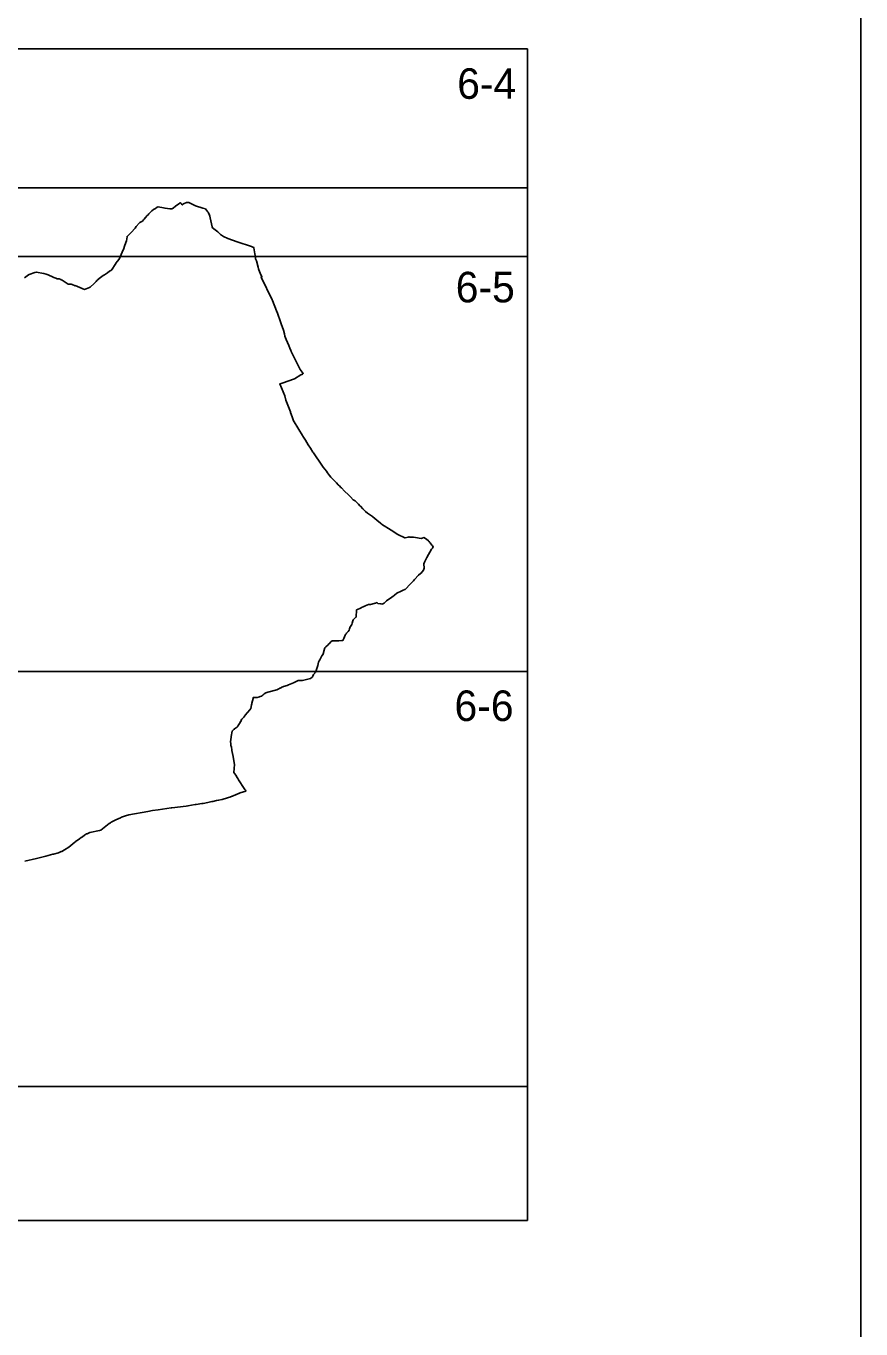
# Model space of a CAD drawing. Extents: x -449577 to -436680, y -1132317 to -1125726.
# Drawn here: x -441418.4 to -441167.1, y -1131954.1 to -1131561.7 of the extents above; entities that cross this region are included whole.
import ezdxf

# ---------------------------------------------------------------- set-up
doc = ezdxf.new("R2010")
doc.units = 0
for name, color, linetype in [('Vrstva 1', 7, 'Continuous'), ('Vrstva 10', 7, 'Continuous'), ('Vrstva 4', 7, 'Continuous')]:
    doc.layers.add(name, color=color, linetype=linetype)

msp = doc.modelspace()

# ---------------------------------------------------------------- linework, layer by layer
at = {"layer": 'Vrstva 1'}
msp.add_lwpolyline([(-442652.08, -1131267.17), (-442652.08, -1132317.17), (-441167.08, -1132317.17), (-441167.08, -1131267.17)], close=True, dxfattribs=at)
msp.add_lwpolyline([(-441418.79, -1131813.29), (-441415.25, -1131812.42), (-441412.48, -1131811.75), (-441411.81, -1131811.54), (-441410.32, -1131811.18), (-441410.11, -1131811.12), (-441408.68, -1131810.73), (-441408.08, -1131810.47), (-441407.86, -1131810.37), (-441407.7, -1131810.31), (-441406.88, -1131809.86), (-441406.82, -1131809.82), (-441405.51, -1131809.04), (-441404.36, -1131807.99), (-441403.71, -1131807.49), (-441403.58, -1131807.38), (-441403.56, -1131807.37), (-441403.4, -1131807.24), (-441403.25, -1131807.14), (-441402.45, -1131806.58), (-441402.39, -1131806.54), (-441402.32, -1131806.49), (-441401.81, -1131806.14), (-441401.44, -1131805.88), (-441400.78, -1131805.42), (-441400.19, -1131805.01), (-441400.03, -1131805.04), (-441400.02, -1131805.04), (-441400, -1131805.02), (-441399.27, -1131804.63), (-441396.31, -1131804.05), (-441395.89, -1131803.9), (-441393.86, -1131802.27), (-441393.39, -1131801.93), (-441393.36, -1131801.91), (-441393, -1131801.65), (-441392.82, -1131801.53), (-441391.43, -1131800.83), (-441390.02, -1131800.19), (-441389.72, -1131800.04), (-441388.46, -1131799.58), (-441387.46, -1131799.33), (-441381.75, -1131798.27), (-441380.33, -1131798.01), (-441378.62, -1131797.76), (-441374.75, -1131797.19), (-441374.51, -1131797.16), (-441370.21, -1131796.64), (-441369.68, -1131796.58), (-441367.53, -1131796.22), (-441367.21, -1131796.17), (-441365.55, -1131795.9), (-441365.15, -1131795.83), (-441363.74, -1131795.54), (-441362.45, -1131795.27), (-441362.24, -1131795.23), (-441361.07, -1131795), (-441360.4, -1131794.87), (-441360.38, -1131794.87), (-441359.47, -1131794.66), (-441359.4, -1131794.64), (-441358.75, -1131794.48), (-441358.4, -1131794.37), (-441357.51, -1131794.08), (-441357.07, -1131793.93), (-441356.42, -1131793.69), (-441356.3, -1131793.65), (-441355.21, -1131793.16), (-441355.21, -1131793.16), (-441355.09, -1131793.12), (-441354.44, -1131792.89), (-441354.35, -1131792.86), (-441353.92, -1131792.7), (-441352.26, -1131792.12), (-441352.28, -1131792.07), (-441352.39, -1131791.9), (-441352.55, -1131791.67), (-441352.77, -1131791.35), (-441354.47, -1131788.71), (-441354.68, -1131788.36), (-441354.85, -1131788.09), (-441355.29, -1131787.38), (-441355.82, -1131786.53), (-441355.66, -1131784.17), (-441355.65, -1131784.08), (-441356.04, -1131781.78), (-441356.04, -1131781.76), (-441356.05, -1131781.74), (-441356.05, -1131781.74), (-441356.05, -1131781.71), (-441356.46, -1131779.88), (-441356.47, -1131779.69), (-441356.53, -1131778.89), (-441356.63, -1131778.61), (-441356.64, -1131778.59), (-441356.75, -1131778.37), (-441356.79, -1131778.29), (-441356.8, -1131777.91), (-441356.83, -1131777.21), (-441356.78, -1131776.72), (-441356.78, -1131776.7), (-441356.69, -1131775.84), (-441356.67, -1131775.73), (-441356.38, -1131774.09), (-441356.3, -1131774.01), (-441356, -1131773.67), (-441355.94, -1131773.6), (-441355.68, -1131773.48), (-441355.62, -1131773.42), (-441355.36, -1131773.22), (-441355.13, -1131773.04), (-441354.92, -1131772.88), (-441354.86, -1131772.84), (-441354.78, -1131772.71), (-441354.7, -1131772.59), (-441354.59, -1131772.42), (-441354.37, -1131772.09), (-441353.95, -1131771.44), (-441353.82, -1131771.19), (-441353.81, -1131771.18), (-441353.67, -1131770.89), (-441353.62, -1131770.8), (-441353.44, -1131770.47), (-441353.3, -1131770.32), (-441353, -1131770.01), (-441352.83, -1131769.83), (-441352.55, -1131769.48), (-441352.42, -1131769.31), (-441351.73, -1131768.46), (-441351.07, -1131767.65), (-441350.78, -1131767.29), (-441350.54, -1131766.12), (-441350.48, -1131765.89), (-441350.41, -1131765.61), (-441350.09, -1131764.3), (-441350.01, -1131764.02), (-441350.01, -1131763.99), (-441349.99, -1131763.94), (-441349.83, -1131763.93), (-441349.81, -1131763.93), (-441349.57, -1131763.93), (-441348.88, -1131763.91), (-441348.87, -1131763.91), (-441348.84, -1131763.91), (-441348.16, -1131763.73), (-441347.96, -1131763.67), (-441347.54, -1131763.56), (-441347.52, -1131763.55), (-441347.46, -1131763.49), (-441347.16, -1131763.21), (-441347.04, -1131763.13), (-441346.7, -1131762.87), (-441346.28, -1131762.55), (-441346.21, -1131762.53), (-441345.65, -1131762.37), (-441342.95, -1131761.61), (-441342.36, -1131761.34), (-441342.03, -1131761.18), (-441341.98, -1131761.16), (-441341.88, -1131761.11), (-441341.52, -1131760.93), (-441341.47, -1131760.91), (-441341.44, -1131760.89), (-441341.43, -1131760.89), (-441341.4, -1131760.87), (-441341.09, -1131760.72), (-441341.03, -1131760.68), (-441340.92, -1131760.63), (-441339.84, -1131760.3), (-441339.41, -1131760.12), (-441338.89, -1131759.9), (-441337.88, -1131759.49), (-441336.46, -1131758.86), (-441336.32, -1131758.85), (-441335.19, -1131758.8), (-441332.79, -1131758.24), (-441332.26, -1131757.84), (-441332.19, -1131757.72), (-441332.1, -1131757.54), (-441331.84, -1131757.03), (-441331.49, -1131756.6), (-441331.47, -1131756.57), (-441331.26, -1131756.28), (-441331.15, -1131756.12), (-441331.14, -1131756.11), (-441330.6, -1131754.33), (-441330.59, -1131754.3), (-441330.39, -1131753.35), (-441330.13, -1131752.89), (-441329.94, -1131752.56), (-441329.39, -1131751.44), (-441329.01, -1131750.93), (-441328.98, -1131750.8), (-441328.91, -1131750.5), (-441328.88, -1131750.36), (-441328.82, -1131750.11), (-441328.8, -1131750.01), (-441328.48, -1131749), (-441328.47, -1131748.99), (-441328.18, -1131748.71), (-441327.52, -1131748.08), (-441327.47, -1131748.03), (-441327, -1131747.55), (-441326.74, -1131747.29), (-441326.64, -1131747.18), (-441326.27, -1131746.86), (-441326.23, -1131746.86), (-441326.22, -1131746.86), (-441325.81, -1131746.85), (-441325.64, -1131746.86), (-441325.01, -1131746.88), (-441324.3, -1131746.88), (-441323.33, -1131746.79), (-441323.3, -1131746.79), (-441323.05, -1131746.76), (-441322.83, -1131746.4), (-441322.78, -1131746.27), (-441322.76, -1131746.22), (-441322.74, -1131746.16), (-441322.38, -1131745.14), (-441322.24, -1131744.97), (-441322.14, -1131744.86), (-441322.1, -1131744.82), (-441322.04, -1131744.74), (-441321.92, -1131744.61), (-441321.65, -1131744.29), (-441321.56, -1131744.19), (-441321.46, -1131744.07), (-441321.12, -1131743.68), (-441321.05, -1131743.29), (-441320.99, -1131742.98), (-441320.92, -1131742.85), (-441320.37, -1131741.93), (-441320.26, -1131741.54), (-441320.07, -1131740.84), (-441319.95, -1131740.55), (-441319.66, -1131740.28), (-441319.11, -1131739.77), (-441319.04, -1131739.71), (-441318.94, -1131737.6), (-441317.92, -1131737.11), (-441317.52, -1131736.9), (-441317.27, -1131736.77), (-441316.98, -1131736.61), (-441316.76, -1131736.53), (-441316.42, -1131736.4), (-441316.37, -1131736.39), (-441315.28, -1131735.98), (-441315.27, -1131735.98), (-441314.78, -1131735.92), (-441314.7, -1131735.9), (-441313.67, -1131735.64), (-441313.52, -1131735.6), (-441313.43, -1131735.57), (-441313.26, -1131735.52), (-441312.73, -1131735.35), (-441312.73, -1131735.35), (-441312.72, -1131735.36), (-441312.72, -1131735.36), (-441312.69, -1131735.42), (-441312.56, -1131735.64), (-441311.68, -1131735.74), (-441311.48, -1131735.76), (-441311.12, -1131735.8), (-441311.03, -1131735.76), (-441310.6, -1131735.58), (-441309.95, -1131734.87), (-441308.31, -1131733.71), (-441308.22, -1131733.64), (-441308.05, -1131733.53), (-441307.54, -1131733.11), (-441306.79, -1131732.51), (-441305.52, -1131731.94), (-441304.9, -1131731.67), (-441304.36, -1131731.43), (-441304.3, -1131731.4), (-441302.65, -1131729.73), (-441301.81, -1131728.84), (-441301.45, -1131728.46), (-441300.26, -1131727.1), (-441299.66, -1131726.64), (-441299.61, -1131726.6), (-441298.77, -1131725.59), (-441298.57, -1131725.02), (-441298.66, -1131723.69), (-441298.44, -1131723.2), (-441297.8, -1131721.75), (-441296.34, -1131719.27), (-441296.31, -1131719.22), (-441296.31, -1131719.22), (-441296.29, -1131719.19), (-441296.26, -1131719.15), (-441296.11, -1131718.96), (-441295.85, -1131718.62), (-441296.11, -1131718.32), (-441296.25, -1131718.1), (-441296.72, -1131717.36), (-441296.92, -1131717.17), (-441297.07, -1131717.01), (-441297.26, -1131716.81), (-441297.84, -1131716.24), (-441298.69, -1131715.77), (-441299.14, -1131715.95), (-441299.47, -1131716.07), (-441301.22, -1131715.8), (-441301.83, -1131715.71), (-441301.97, -1131715.7), (-441302.56, -1131715.68), (-441302.94, -1131715.63), (-441303.1, -1131715.6), (-441303.14, -1131715.6), (-441303.17, -1131715.59), (-441303.17, -1131715.59), (-441303.2, -1131715.6), (-441303.3, -1131715.63), (-441303.43, -1131715.66), (-441304.33, -1131715.9), (-441304.4, -1131715.87), (-441306.47, -1131714.83), (-441308.49, -1131713.55), (-441311.4, -1131711.73), (-441311.56, -1131711.59), (-441311.6, -1131711.56), (-441311.69, -1131711.48), (-441312.83, -1131710.55), (-441313.98, -1131709.5), (-441314.09, -1131709.4), (-441315.3, -1131708.64), (-441315.58, -1131708.41), (-441316.21, -1131707.91), (-441316.52, -1131707.67), (-441317.02, -1131707.14), (-441317.74, -1131706.38), (-441317.89, -1131706.22), (-441318.35, -1131705.73), (-441319.32, -1131704.7), (-441319.52, -1131704.59), (-441319.52, -1131704.59), (-441319.7, -1131704.5), (-441319.9, -1131704.4), (-441320.73, -1131703.57), (-441321.36, -1131702.94), (-441322.54, -1131701.77), (-441323.47, -1131700.83), (-441323.63, -1131700.68), (-441324.07, -1131700.23), (-441324.31, -1131699.99), (-441324.4, -1131699.9), (-441324.44, -1131699.86), (-441324.96, -1131699.34), (-441325.6, -1131698.69), (-441325.68, -1131698.61), (-441325.7, -1131698.59), (-441325.85, -1131698.44), (-441326.68, -1131697.6), (-441327.06, -1131697.1), (-441327.34, -1131696.73), (-441327.66, -1131696.3), (-441328.02, -1131695.82), (-441328.97, -1131694.56), (-441329.34, -1131694.02), (-441331.88, -1131690.28), (-441332.05, -1131690.02), (-441332.82, -1131688.83), (-441333.49, -1131687.82), (-441334.33, -1131686.49), (-441335.13, -1131685.22), (-441335.21, -1131685.09), (-441336.3, -1131683.24), (-441337.98, -1131680.39), (-441337.98, -1131680.38), (-441337.98, -1131680.38), (-441337.99, -1131680.38), (-441338.32, -1131679.4), (-441338.77, -1131678.1), (-441338.83, -1131677.9), (-441340.21, -1131674.39), (-441340.5, -1131673.14), (-441341.98, -1131669.46), (-441341.35, -1131669.26), (-441337.63, -1131668.02), (-441335.66, -1131666.8), (-441335.48, -1131666.69), (-441335.42, -1131666.65), (-441335.22, -1131666.53), (-441334.95, -1131666.36), (-441335.87, -1131665.17), (-441337.28, -1131662.39), (-441338.03, -1131660.92), (-441338.56, -1131659.76), (-441338.58, -1131659.72), (-441338.64, -1131659.59), (-441338.65, -1131659.56), (-441338.67, -1131659.53), (-441338.71, -1131659.44), (-441339.04, -1131658.71), (-441339.36, -1131657.92), (-441340.07, -1131656.15), (-441340.48, -1131655.11), (-441340.63, -1131654.48), (-441340.89, -1131653.35), (-441341.63, -1131651.46), (-441341.83, -1131650.86), (-441342.77, -1131648.23), (-441343.04, -1131647.51), (-441344.23, -1131644.42), (-441344.3, -1131644.24), (-441344.33, -1131644.16), (-441347.68, -1131637.35), (-441347.37, -1131637.21), (-441347.35, -1131637.2), (-441347.45, -1131637.03), (-441347.53, -1131636.93), (-441347.7, -1131636.7), (-441347.76, -1131636.62), (-441348.37, -1131635.14), (-441348.42, -1131634.85), (-441348.52, -1131634.39), (-441348.53, -1131634.33), (-441349.04, -1131632.49), (-441349.34, -1131631.86), (-441349.35, -1131631.78), (-441349.39, -1131631.42), (-441349.53, -1131630.33), (-441349.81, -1131628.49), (-441349.87, -1131628.47), (-441350.17, -1131628.37), (-441350.55, -1131628.11), (-441350.56, -1131628.11), (-441354.86, -1131626.7), (-441357.65, -1131625.72), (-441358.96, -1131625.1), (-441359.93, -1131624.54), (-441360.65, -1131623.76), (-441362.33, -1131622.49), (-441362.39, -1131622.19), (-441362.97, -1131619.49), (-441363.12, -1131618.95), (-441363.3, -1131618.44), (-441363.35, -1131618.28), (-441363.6, -1131617.76), (-441363.85, -1131617.45), (-441364.43, -1131616.76), (-441365.18, -1131616.55), (-441367.36, -1131615.89), (-441369.45, -1131614.93), (-441370.07, -1131614.93), (-441371.02, -1131615.3), (-441371.15, -1131615.39), (-441371.22, -1131615.44), (-441371.36, -1131615.54), (-441371.4, -1131615.57), (-441371.42, -1131615.55), (-441371.63, -1131615.3), (-441371.88, -1131615.02), (-441371.96, -1131614.92), (-441372.05, -1131614.96), (-441372.56, -1131615.35), (-441372.75, -1131615.5), (-441373.42, -1131616.02), (-441374.17, -1131616.58), (-441374.51, -1131616.8), (-441375.1, -1131616.76), (-441376.58, -1131616.61), (-441377.04, -1131616.52), (-441378.63, -1131616.2), (-441378.93, -1131616.31), (-441379.49, -1131616.66), (-441380.04, -1131616.98), (-441380.53, -1131617.44), (-441381.06, -1131617.93), (-441381.46, -1131618.32), (-441381.47, -1131618.33), (-441381.8, -1131618.67), (-441381.93, -1131618.81), (-441382.44, -1131619.36), (-441382.89, -1131619.91), (-441383.05, -1131620.1), (-441383.41, -1131620.53), (-441384.15, -1131620.86), (-441384.17, -1131620.86), (-441384.37, -1131621.11), (-441385.23, -1131622.13), (-441385.61, -1131622.58), (-441386.74, -1131623.94), (-441386.75, -1131623.95), (-441387.99, -1131625.12), (-441388.11, -1131625.96), (-441388.16, -1131626.33), (-441388.2, -1131626.43), (-441388.68, -1131627.78), (-441389.12, -1131629.02), (-441389.15, -1131629.1), (-441389.45, -1131629.79), (-441390.38, -1131631.97), (-441390.4, -1131631.98), (-441390.97, -1131632.66), (-441391.27, -1131633.01), (-441391.27, -1131633.02), (-441391.61, -1131633.56), (-441392.48, -1131634.95), (-441392.57, -1131635.09), (-441392.74, -1131635.22), (-441393.27, -1131635.61), (-441393.88, -1131636.06), (-441393.88, -1131636.06), (-441394.85, -1131636.69), (-441394.98, -1131636.78), (-441395.16, -1131636.9), (-441396.46, -1131637.76), (-441396.47, -1131637.77), (-441396.73, -1131638.03), (-441396.85, -1131638.15), (-441397.07, -1131638.38), (-441397.35, -1131638.66), (-441397.92, -1131639.23), (-441399.08, -1131640.39), (-441399.28, -1131640.47), (-441400.78, -1131641.04), (-441403.59, -1131639.92), (-441403.59, -1131639.93), (-441403.6, -1131639.95), (-441404.51, -1131639.57), (-441404.82, -1131639.44), (-441404.84, -1131639.44), (-441405.23, -1131639.44), (-441405.71, -1131639.44), (-441407.27, -1131638.45), (-441407.53, -1131638.32), (-441407.82, -1131638.16), (-441407.88, -1131638.13), (-441407.92, -1131638.11), (-441408.46, -1131637.88), (-441408.51, -1131637.88), (-441408.52, -1131637.88), (-441408.67, -1131637.87), (-441408.79, -1131637.86), (-441409.1, -1131637.84), (-441409.12, -1131637.84), (-441409.12, -1131637.84), (-441409.23, -1131637.8), (-441409.47, -1131637.7), (-441410.07, -1131637.45), (-441410.23, -1131637.38), (-441411.75, -1131636.65), (-441412.37, -1131636.47), (-441413.04, -1131636.27), (-441415.36, -1131635.84), (-441415.37, -1131635.84), (-441415.77, -1131635.95), (-441417.51, -1131636.53), (-441417.64, -1131636.64), (-441418.85, -1131637.6)], dxfattribs=at)
at = {"layer": 'Vrstva 10'}
msp.add_lwpolyline([(-441267.49, -1131610.43), (-441267.49, -1131921.41), (-441600.36, -1131921.41), (-441600.36, -1131756.11), (-441579.99, -1131756.11), (-441579.99, -1131631.11), (-441579.99, -1131610.43), (-441267.49, -1131610.43)], dxfattribs=at)
at = {"layer": 'Vrstva 4'}
msp.add_line((-441579.99, -1131568.61), (-441267.49, -1131568.61), dxfattribs=at)
msp.add_lwpolyline([(-441267.49, -1131568.61), (-441267.49, -1131631.11), (-441423.74, -1131631.11), (-441423.74, -1131568.61)], dxfattribs=at)
for points in [[(-441267.49, -1131631.11), (-441267.49, -1131756.11), (-441423.74, -1131756.11), (-441423.74, -1131631.11)], [(-441267.49, -1131756.11), (-441267.49, -1131881.11), (-441423.74, -1131881.11), (-441423.74, -1131756.11)]]:
    msp.add_lwpolyline(points, close=True, dxfattribs=at)

# ---------------------------------------------------------------- texts
at = {"layer": 'Vrstva 1'}
for s, p in [('6-4', (-441288.62, -1131583.66)), ('6-5', (-441289.07, -1131644.95)), ('6-6', (-441289.44, -1131771.02))]:
    msp.add_text(s, height=9.2, dxfattribs=at).set_placement(p)

doc.saveas('drawing.dxf')
